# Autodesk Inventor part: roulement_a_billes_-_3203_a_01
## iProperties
Shininess: 64.0
Length Units: 11269
Angle Units: 11279
Time Units: 11290
Mass Units: 11283
Length Display Precision: 3
Angle Display Precision: 2
Compacted: True
Part Number: roulement_a_billes_-_3203_a_01
Document SubType Name: Modeling
Created: 2005-02
Material: Par défaut
Designer: LEGERET Philippe
Density: 0.0
Volumn: 0.0
Area: 0.0
PropertySet Name: Model Information
Control State: 0
Master: False
Checked Out: False
Author: LEGERET Philippe
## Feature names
1. Base1
